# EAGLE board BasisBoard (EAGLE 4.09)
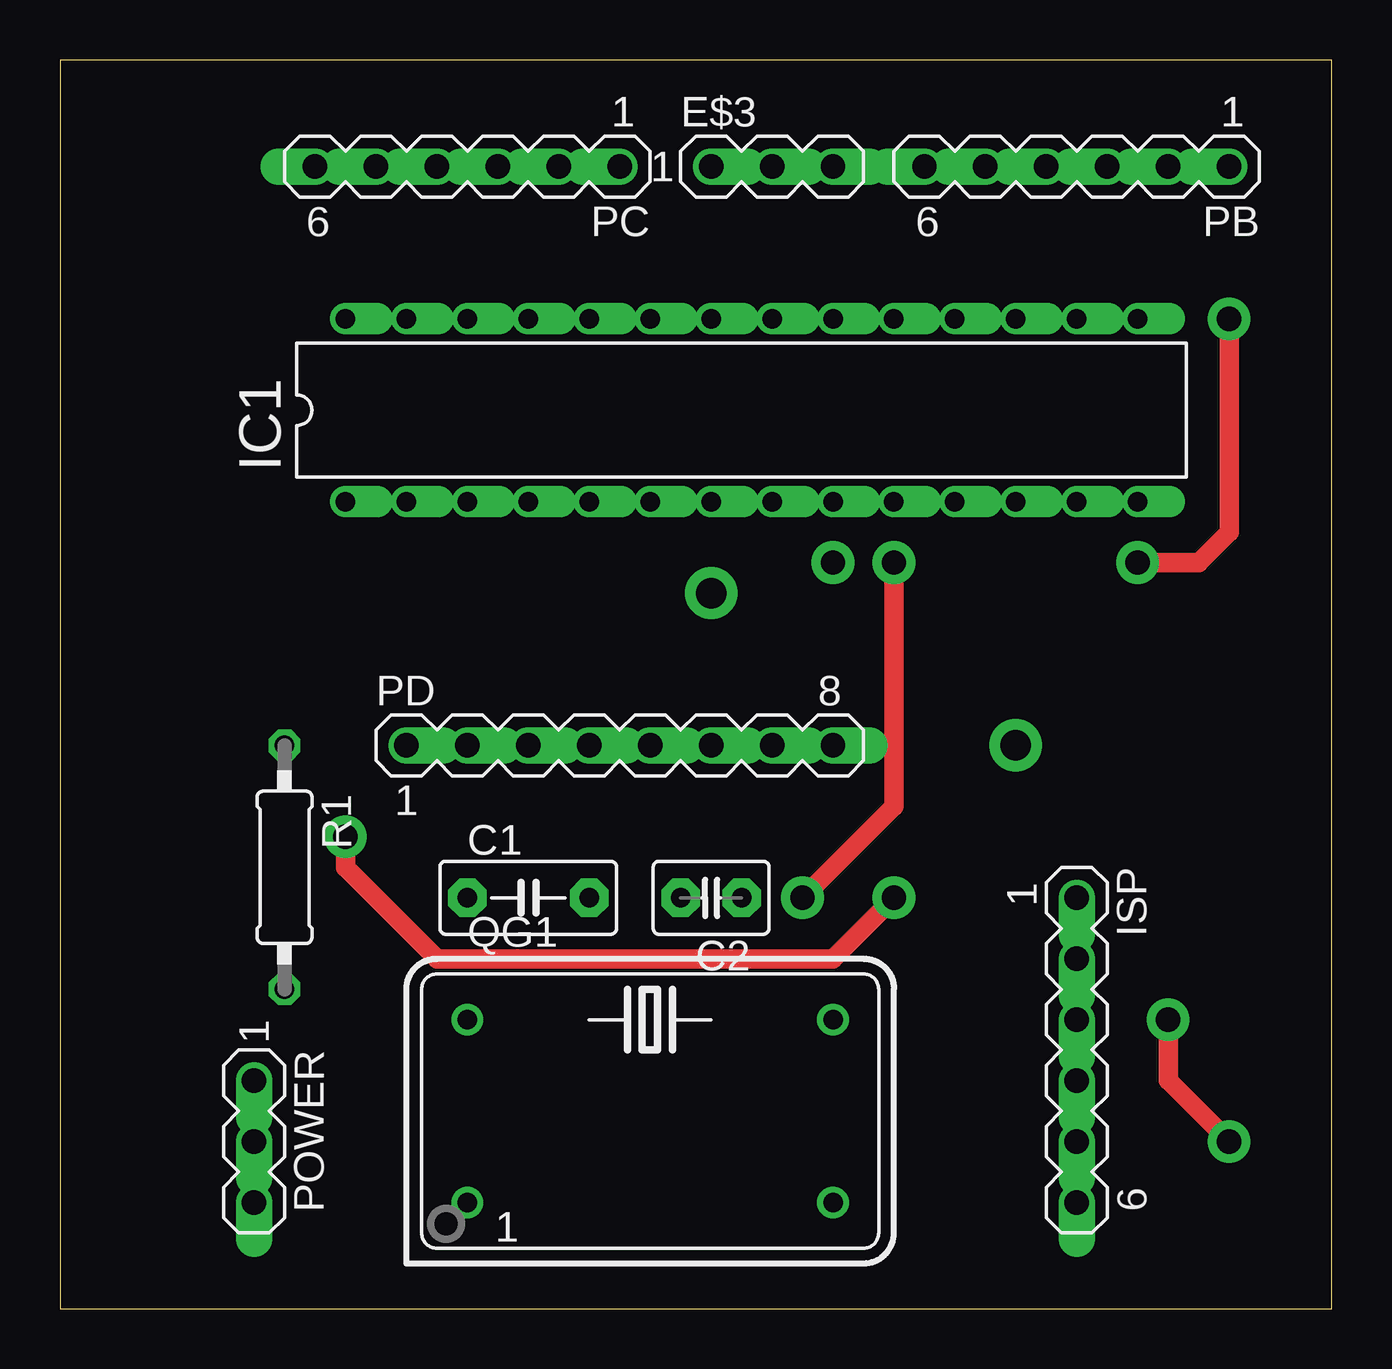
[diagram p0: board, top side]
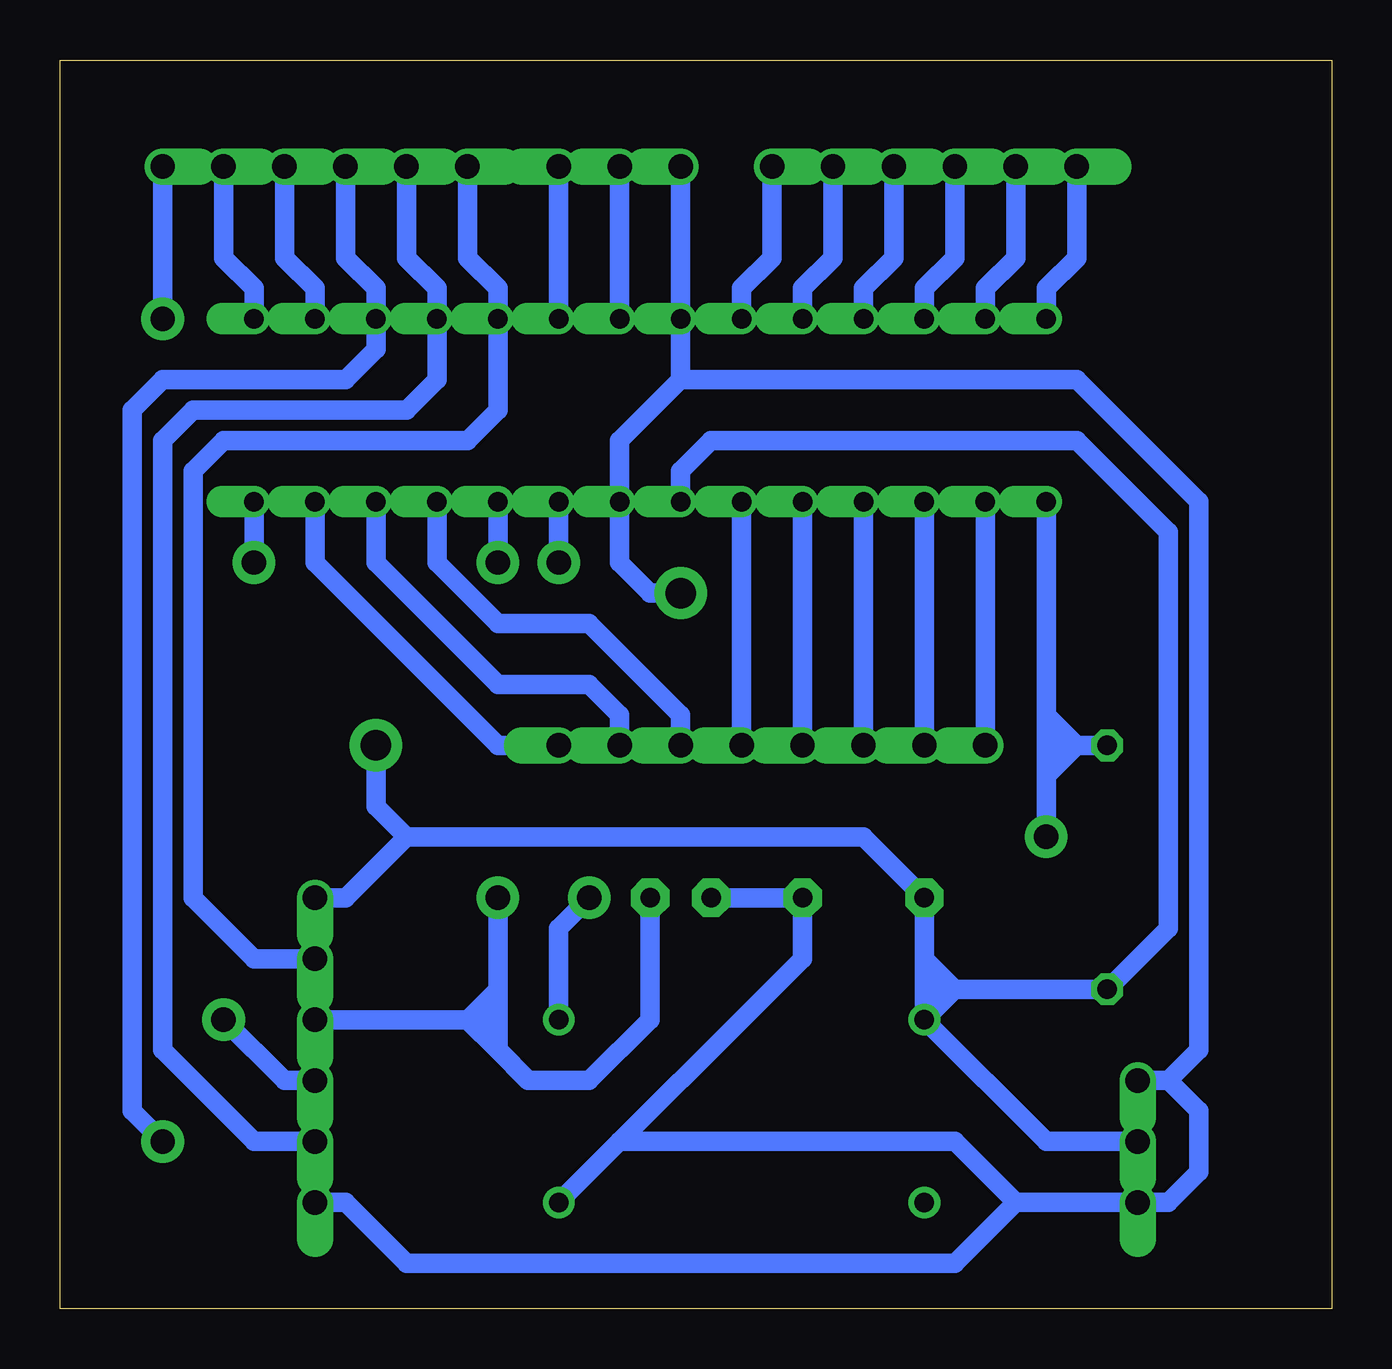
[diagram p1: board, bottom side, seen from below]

Size 53.01 x 52.06 mm. Coordinates in mm from the lower left corner, seen from the top.
Outline: 0,0 53.01,0 53.01,52.06 0,52.06 0,0
Copper layers used: Top, Bottom

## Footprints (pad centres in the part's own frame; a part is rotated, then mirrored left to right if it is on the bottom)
C5B3 = drill 0.813 pad 1.6 octagon: 1 -2.54,0; 2 2.54,0
C2.5-3 = drill 0.813 pad 1.6 octagon: 1 -1.27,0; 2 1.27,0
MA03-1 = drill 1.016 offset: 1 -2.54,0; 2 0,0; 3 2.54,0
DIL28-3 = drill 0.813 offset: 1 -16.51,-3.81; 2 -13.97,-3.81; 3 -11.43,-3.81; 4 -8.89,-3.81; 5 -6.35,-3.81; 6 -3.81,-3.81; 7 -1.27,-3.81; 8 1.27,-3.81; 9 3.81,-3.81; 10 6.35,-3.81; 11 8.89,-3.81; 12 11.43,-3.81; 13 13.97,-3.81; 14 16.51,-3.81; 15 16.51,3.81; 16 13.97,3.81; 17 11.43,3.81; 18 8.89,3.81; 19 6.35,3.81; 20 3.81,3.81; 21 1.27,3.81; 22 -1.27,3.81; 23 -3.81,3.81; 24 -6.35,3.81; 25 -8.89,3.81; 26 -11.43,3.81; 27 -13.97,3.81; 28 -16.51,3.81
MA06-1 = drill 1.016 offset: 1 -6.35,0; 2 -3.81,0; 3 -1.27,0; 4 1.27,0; 5 3.81,0; 6 6.35,0
MA08-1 = drill 1.016 offset: 1 -8.89,0; 2 -6.35,0; 3 -3.81,0; 4 -1.27,0; 5 1.27,0; 6 3.81,0; 7 6.35,0; 8 8.89,0
DIL14S = drill 0.813 round: 1 -7.62,-3.81; 7 7.62,-3.81; 8 7.62,3.81; 14 -7.62,3.81
0207/10 = drill 0.813 octagon: 1 -5.08,0; 2 5.08,0

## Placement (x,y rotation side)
C1  100nF  [C5B3]  19.52,17.14 0 top
C2  47pF  [C2.5-3]  27.14,17.14 180 top
E$3  [MA03-1]  29.68,47.62 0 top
IC1  AT90S4433P  [DIL28-3]  28.41,37.46 0 top
ISP  [MA06-1]  42.38,10.79 270 top
PB  [MA06-1]  42.38,47.62 180 top
PC  [MA06-1]  16.98,47.62 180 top
PD  [MA08-1]  23.33,23.49 0 top
POWER  [MA03-1]  8.09,6.98 270 top
QG1  [DIL14S]  24.6,8.25 0 top
R1  10k  [0207/10]  9.36,18.41 270 top

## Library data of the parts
C1 C2 = capacitor-wima
E$3 ISP PB PC PD POWER = con-lstb
IC1 = atmel
QG1 = crystal
R1 = rcl

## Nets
+5V: C1.1 IC1.7 ISP.1 POWER.2 QG1.14 R1.2
AREF: E$3.2 IC1.21
AVCC: E$3.3 IC1.20
GND: C1.2 C2.2 E$3.1 IC1.8 IC1.22 ISP.6 POWER.1 POWER.3 QG1.7
N$1: IC1.10 QG1.8
N$2: C2.1 IC1.1 ISP.3 R1.1
N$3: IC1.19 ISP.2 PB.6
N$4: IC1.18 ISP.5 PB.5
N$5: IC1.17 ISP.4 PB.4
S$1: IC1.28 PC.6
S$2: IC1.27 PC.5
S$3: IC1.26 PC.4
S$4: IC1.25 PC.3
S$5: IC1.24 PC.2
S$6: IC1.23 PC.1
S$7: IC1.2 PD.1
S$8: IC1.14 PB.1
S$9: IC1.9
S$10: IC1.3 PD.2
S$11: IC1.4 PD.3
S$12: IC1.5 PD.4
S$13: IC1.16 PB.3
S$14: IC1.15 PB.2
S$15: IC1.6 PD.5
S$16: IC1.11 PD.6
S$17: IC1.12 PD.7
S$18: IC1.13 PD.8

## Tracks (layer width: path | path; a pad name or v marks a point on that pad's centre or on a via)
+5V  (via drill 1.27 pad 2.18)
  Bottom 0.813: 16.98,14.6 C1.1 | POWER.2 11.9,6.98 QG1.14 | 38.57,19.68 41.11,17.14 ISP.1 | 15.71,13.33 R1.2 | QG1.14 15.71,13.33 | QG1.14 16.98,13.33 | 16.98,13.33 16.98,14.6 | 15.71,13.33 16.98,14.6 | 15.71,13.33 16.98,13.33 | 38.57,19.68 19.52,19.68 C1.1 | C1.1 16.98,13.33 | 16.98,13.33 R1.2 | R1.2 6.82,15.87 6.82,32.38 10.63,36.19 25.87,36.19 27.14,34.92 IC1.7 | 38.57,19.68 39.84,20.95 v39.84,23.49
AREF
  Bottom 0.813: E$3.2 IC1.21
AVCC
  Bottom 0.813: E$3.3 IC1.20
GND  (via drill 1.27 pad 2.18)
  Bottom 0.813: 13.17,4.44 15.71,1.9 38.57,1.9 41.11,4.44 ISP.6 | 13.17,4.44 POWER.3 6.82,4.44 5.55,5.71 5.55,8.25 6.82,9.52 | 13.17,4.44 15.71,6.98 29.68,6.98 QG1.7 22.06,14.6 C1.2 C2.2 | 27.14,38.73 IC1.22 E$3.1 | 27.14,38.73 29.68,36.19 IC1.8 29.68,31.11 28.41,29.84 v27.14,29.84 | 27.14,38.73 10.63,38.73 5.55,33.65 5.55,10.79 6.82,9.52 | 6.82,9.52 POWER.1
N$1  (via drill 1.02 pad 1.78)
  Top 0.813: v34.76,31.11 34.76,20.95 v30.95,17.14
  Bottom 0.813: IC1.10 v34.76,31.11 | QG1.8 32.22,15.87 v30.95,17.14
N$2  (via drill 1.02 pad 1.78)
  Top 0.813: v11.9,19.68 11.9,18.41 15.71,14.6 32.22,14.6 v34.76,17.14
  Bottom 0.813: R1.1 10.63,23.49 | 10.63,23.49 11.9,24.76 IC1.1 11.9,23.49 | C2.1 28.41,12.06 30.95,9.52 33.49,9.52 34.76,10.79 | 34.76,10.79 36.03,12.06 | v11.9,19.68 11.9,22.22 | 11.9,22.22 10.63,23.49 | 10.63,23.49 11.9,23.49 | ISP.3 36.03,12.06 | 36.03,12.06 34.76,13.33 | 34.76,13.33 v34.76,17.14 | 11.9,23.49 11.9,22.22 | 34.76,10.79 34.76,12.06 | 34.76,13.33 34.76,12.06 | 34.76,12.06 36.03,12.06
N$3
  Bottom 0.813: ISP.2 44.92,14.6 47.46,17.14 47.46,34.92 46.19,36.19 36.03,36.19 34.76,37.46 IC1.19 34.76,42.54 36.03,43.81 PB.6
N$4
  Bottom 0.813: ISP.5 44.92,6.98 48.73,10.79 48.73,36.19 47.46,37.46 38.57,37.46 37.3,38.73 IC1.18 37.3,42.54 38.57,43.81 PB.5
N$5  (via drill 1.02 pad 1.78)
  Top 0.813: v48.73,6.98 46.19,9.52 v46.19,12.06
  Bottom 0.813: v48.73,6.98 50,8.25 50,37.46 48.73,38.73 41.11,38.73 39.84,40 IC1.17 39.84,42.54 41.11,43.81 PB.4 | v46.19,12.06 43.65,9.52 ISP.4
S$1
  Bottom 0.813: PC.6 10.63,43.81 11.9,42.54 IC1.28
S$2
  Bottom 0.813: PC.5 13.17,43.81 14.44,42.54 IC1.27
S$3
  Bottom 0.813: PC.4 15.71,43.81 16.98,42.54 IC1.26
S$4
  Bottom 0.813: PC.3 18.25,43.81 19.52,42.54 IC1.25
S$5
  Bottom 0.813: PC.2 20.79,43.81 22.06,42.54 IC1.24
S$6
  Bottom 0.813: PC.1 23.33,43.81 24.6,42.54 IC1.23
S$7
  Bottom 0.813: IC1.2 PD.1
S$8  (via drill 1.02 pad 1.78)
  Top 0.813: v48.73,41.27 48.73,32.38 47.46,31.11 v44.92,31.11
  Bottom 0.813: v44.92,31.11 IC1.14 | PB.1 v48.73,41.27
S$9  (via drill 1.02 pad 1.78)
  Bottom 0.813: v32.22,31.11 IC1.9
S$10
  Bottom 0.813: IC1.3 PD.2
S$11
  Bottom 0.813: IC1.4 PD.3
S$12
  Bottom 0.813: IC1.5 PD.4
S$13
  Bottom 0.813: PB.3 43.65,43.81 42.38,42.54 IC1.16
S$14
  Bottom 0.813: PB.2 46.19,43.81 44.92,42.54 IC1.15
S$15
  Bottom 0.813: IC1.6 PD.5
S$16
  Bottom 0.813: PD.6 27.14,24.76 30.95,28.57 34.76,28.57 37.3,31.11 IC1.11
S$17
  Bottom 0.813: PD.7 29.68,24.76 30.95,26.03 34.76,26.03 39.84,31.11 IC1.12
S$18
  Bottom 0.813: PD.8 34.76,23.49 42.38,31.11 IC1.13
S$19  (via drill 1.02 pad 1.78)
  other vias: 34.76,31.11
S$20  (via drill 1.02 pad 1.78)
  other vias: 30.95,17.14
